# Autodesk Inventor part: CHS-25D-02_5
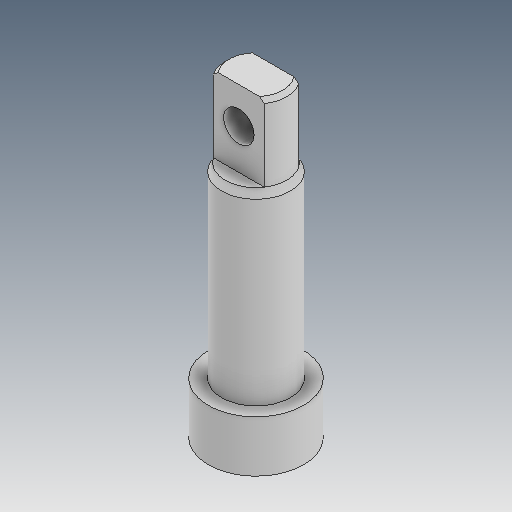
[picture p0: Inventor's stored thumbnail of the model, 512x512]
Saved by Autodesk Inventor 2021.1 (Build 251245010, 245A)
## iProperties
Created: 2019-04
Part Number: CHS-25D-02_5
Material: Ogólny
Document SubType Name: Modeling
Designer: user
Density: 1 g/cm^3
Appearance: Domyślna
Author: user
Revision Number: ÈÎºÎ
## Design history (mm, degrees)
feature "ÊäÈë1"
feature "ÊäÈë2"
node "Bryła1"
node "Bryła2"
